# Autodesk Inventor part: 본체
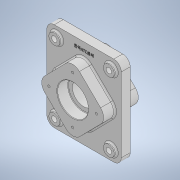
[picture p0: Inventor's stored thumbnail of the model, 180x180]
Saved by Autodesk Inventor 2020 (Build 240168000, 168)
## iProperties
Created: 2021-07
Part Number: 본체
Material: 일반
Document SubType Name: Modeling
Designer: Owner
Density: 1 g/cm^3
Appearance: 기본값
Mass: 809.194 g
Surface Area: 969.936 cm^2
Volume: 809.194 cm^3
Author: Owner
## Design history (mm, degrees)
sketch "스케치1"
  geometry: L1 (-75, 90)-(75, 90); L2 (75, 90)-(75, -90); L3 (75, -90)-(-75, -90); L4 (-75, -90)-(-75, 90); L5 (-75, 90)-(75, -90); L6 (75, 90)-(-75, -90); L7 (0.612, 70.708)-(-70.708, 0.612); L8 (-70.708, 0.612)-(-0.612, -70.708); L9 (-0.612, -70.708)-(70.708, -0.612); L10 (70.708, -0.612)-(0.612, 70.708); L11 (0.612, 70.708)-(-0.612, -70.708); L12 (-70.708, 0.612)-(70.708, -0.612); 8 further points
  constraints: 24 end point, 9 midpoint, 4 parallel, 2 coincident, 2 perpendicular, 1 horizontal, 1 horizontal alignment
  dimensions: "d0" = 180 distance of L1.end L2.end; "d1" = 150 distance of L1.start L1.end; "d2" = 100 distance of L8.end L7.end; "d3" = 100 distance of L8.end L9.end
extrude "돌출1" new body sketch "스케치1" stored distance "d4" = 70; taper "d5" = 0 deg
sketch "스케치2"
  geometry: C1 r 31 at (0, 0); 1 further point
  constraints: 1 centre point, 1 coincident
  dimensions: "d7" = 62 diameter of C1
sketch "스케치3"
  geometry: 2 further points
  constraints: 1 coincident
node "작업 평면1"
sketch "스케치4"
  geometry: L1 (90, -75)-(-90, -75); L2 (-90, -75)-(-90, 75); L3 (-90, 75)-(90, 75); L4 (90, 75)-(90, -75); L5 (90, -75)-(-90, 75); L6 (-90, -75)-(90, 75); 1 further point
  constraints: 12 end point, 2 midpoint, 2 parallel, 1 horizontal, 1 perpendicular
  dimensions: "d23" = 180 distance of L2.end L3.end; "d24" = 150 distance of L1.end L2.end
extrude "돌출2" join sketch "스케치4" distance "d25" = 18; taper "d26" = 0 deg
fillet "모깎기1" dims "d27" = 15
fillet "모깎기2" dims "d35" = 20
fillet "모깎기3" dims "d36" = 20
hole "구멍4" sketch "스케치3" diameter "d37" = 45; stored, may be unused: countersink angle "d41" = 90 deg, drill point angle "d43" = 118 deg; dims "d38" = 10, "d39" = 62, "d40" = 22, "d42" = 13
sketch "스케치6"
  geometry: L1 (-70, -55)-(70, -55); L2 (-70, -55)-(-70, 55); L3 (-70, 55)-(70, 55); C1 r 11 at (70, -55); C2 r 11 at (-70, -55); C3 r 11 at (70, 55); C4 r 11 at (-70, 55); 3 further points
  constraints: 6 end point, 4 centre point, 2 horizontal, 2 midpoint, 2 vertical alignment, 1 horizontal alignment, 1 vertical
  dimensions: "d44" = 140 distance of L1.start L1.end; "d45" = 22 diameter of C1; "d46" = 22 diameter of C2; "d49" = 22 diameter of C3; "d50" = 22 diameter of C4; "d51" = 110 distance of L2.end L1.start
extrude "돌출3" join sketch "스케치6" distance "d47" = 5; taper "d48" = 0 deg
sketch "스케치7"
  geometry: C1 r 11 at (0, 0) reference; 2 further points
  constraints: 1 coincident
hole "구멍5" sketch "스케치7" at (0, 0) diameter "d52" = 11; stored, may be unused: countersink angle "d56" = 90 deg, drill point angle "d58" = 118 deg; dims "d53" = 22, "d54" = 62, "d55" = 22, "d57" = 29.3
fillet "모깎기4" dims "d59" = 3
fillet "모깎기5" dims "d60" = 3
fillet "모깎기6" dims "d61" = 3
sketch "스케치10"
  geometry: L1 (90, -60)-(90, 60) reference; 2 further points
  constraints: 1 horizontal alignment, 1 other
  dimensions: "d82" = 15 distance from line of L1 point (75, 0)
feature "엠보싱1" sketch "스케치10" dims "d0" = 180, "d1" = 150, "d2" = 100, "d3" = 100, "d23" = 180, "d24" = 150, "d83" = 0.5, "d84" = 0
extrude "돌출4" cut sketch "스케치2" distance "d85" = 22; taper "d86" = 0 deg
sketch "스케치11" dims "d93" = 96
  geometry: 3 further points
  constraints: 2 vertical alignment, 1 coincident, 2 other
hole "구멍8" sketch "스케치11" at (0, 48) diameter "d94" = 4.917; stored, may be unused: countersink angle "d98" = 90 deg, drill point angle "d100" = 118 deg; dims "d95" = 10, "d96" = 62, "d97" = 22, "d99" = 13
fillet "모깎기7" dims "d104" = 1
chamfer "모따기2" distance "d105" = 1; stored, may be unused: second distance "d106" = 2, angle "d107" = 45 deg
node "솔리드1"
mirror "미러1"
mirror "미러2"
pattern_circular "원형 패턴4" dims angle "d102" = 360 deg
mirror "미러3"
feature "A9D066F2-1C7D-4E18-AEED-F7BC21143FA4" dims "d37" = 45, "d38" = 10, "d39" = 62, "d40" = 22, "d41" = 90 deg, "d42" = 13, "d43" = 118 deg
other parameters: "d22" = -41
